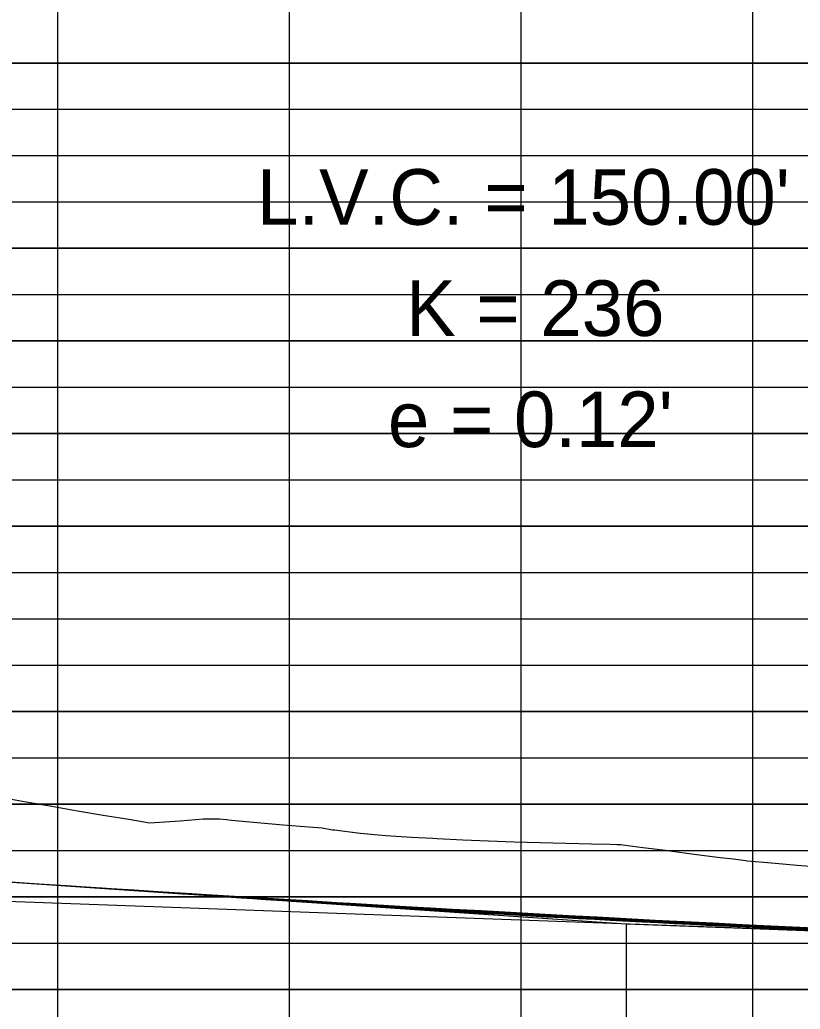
# Model space of a CAD drawing. Extents: x 1195880 to 1289360, y 2059330 to 2086925.
# Drawn here: x 1197302.3 to 1197386.5, y 2059658.6 to 2059765.4 of the extents above; entities that cross this region are included whole.
import ezdxf

# ---------------------------------------------------------------- set-up
doc = ezdxf.new("R2010")
doc.units = 0
for name, color, linetype in [('Default', 7, 'Continuous'), ('Existing Ground PGL', 7, 'Continuous'), ('Grid', 7, 'Continuous'), ('Profile', 7, 'Continuous'), ('Profile Annotation', 7, 'Continuous')]:
    doc.layers.add(name, color=color, linetype=linetype)

msp = doc.modelspace()

# ---------------------------------------------------------------- linework, layer by layer
for p, q in [((1197188.59, 2059680.04), (1197367.71, 2059667.81)), ((1197188.59, 2059680.04), (1197367.71, 2059667.81)), ((1197253.56, 2059675.6), (1197367.71, 2059667.81)), ((1197253.56, 2059675.6), (1197326.4, 2059670.63)), ((1197253.56, 2059675.6), (1197317.71, 2059671.22)), ((1197253.56, 2059675.6), (1197323.22, 2059670.85)), ((1197253.56, 2059675.6), (1197322.71, 2059670.88)), ((1197253.56, 2059675.6), (1197317.71, 2059671.22)), ((1197253.56, 2059675.6), (1197320.21, 2059671.05)), ((1197263.59, 2059674.92), (1197320.21, 2059671.05)), ((1197268.59, 2059674.58), (1197320.21, 2059671.05)), ((1197273.59, 2059674.23), (1197320.21, 2059671.05)), ((1197273.59, 2059674.23), (1197307.21, 2059671.94)), ((1197273.59, 2059674.23), (1197305.21, 2059672.08)), ((1197273.59, 2059674.23), (1197302.71, 2059672.25)), ((1197367.71, 2059667.81), (1197516.64, 2059662.37)), ((1197367.71, 2059667.81), (1197516.64, 2059662.37)), ((1197367.71, 2059667.81), (1197516.64, 2059662.37))]:
    msp.add_line(p, q)
for points in [[(1197300.21, 2059672.42), (1197303.02, 2059672.23), (1197305.83, 2059672.04), (1197308.65, 2059671.85), (1197311.46, 2059671.66), (1197314.27, 2059671.48), (1197317.08, 2059671.3), (1197319.9, 2059671.12), (1197322.71, 2059670.94), (1197325.52, 2059670.76), (1197328.33, 2059670.59), (1197331.15, 2059670.42), (1197333.96, 2059670.25), (1197336.77, 2059670.08), (1197339.58, 2059669.91), (1197342.4, 2059669.75), (1197345.21, 2059669.58), (1197348.02, 2059669.42), (1197350.83, 2059669.26), (1197353.65, 2059669.1), (1197356.46, 2059668.95), (1197359.27, 2059668.79), (1197362.08, 2059668.64), (1197364.9, 2059668.49), (1197370.52, 2059668.2), (1197373.33, 2059668.05), (1197376.15, 2059667.91), (1197378.96, 2059667.77), (1197381.77, 2059667.63), (1197384.58, 2059667.49), (1197387.4, 2059667.36)], [(1197300.63, 2059672.39), (1197303.54, 2059672.19), (1197306.46, 2059672), (1197309.38, 2059671.81), (1197312.29, 2059671.62), (1197315.21, 2059671.43), (1197318.13, 2059671.24), (1197321.04, 2059671.06), (1197323.96, 2059670.87), (1197326.88, 2059670.69), (1197329.79, 2059670.51), (1197332.71, 2059670.34), (1197335.63, 2059670.16), (1197338.54, 2059669.99), (1197341.46, 2059669.82), (1197344.38, 2059669.65), (1197347.29, 2059669.48), (1197350.21, 2059669.32), (1197353.13, 2059669.15), (1197356.04, 2059668.99), (1197358.96, 2059668.83), (1197361.88, 2059668.67), (1197364.79, 2059668.52), (1197370.63, 2059668.21), (1197373.54, 2059668.06), (1197376.46, 2059667.91), (1197379.38, 2059667.77), (1197382.29, 2059667.62), (1197385.21, 2059667.48), (1197388.13, 2059667.34)], [(1197301.25, 2059672.35), (1197304.27, 2059672.15), (1197307.29, 2059671.95), (1197310.31, 2059671.75), (1197313.33, 2059671.56), (1197316.36, 2059671.36), (1197319.38, 2059671.17), (1197322.4, 2059670.98), (1197325.42, 2059670.8), (1197328.44, 2059670.61), (1197331.46, 2059670.43), (1197334.48, 2059670.25), (1197337.5, 2059670.07), (1197340.52, 2059669.89), (1197343.54, 2059669.71), (1197346.56, 2059669.54), (1197349.58, 2059669.37), (1197352.61, 2059669.2), (1197355.63, 2059669.03), (1197358.65, 2059668.87), (1197361.67, 2059668.7), (1197364.69, 2059668.54), (1197370.73, 2059668.23), (1197373.75, 2059668.07), (1197376.77, 2059667.92), (1197379.79, 2059667.77), (1197382.81, 2059667.62), (1197385.83, 2059667.47), (1197388.86, 2059667.32)], [(1197302.08, 2059672.3), (1197305.21, 2059672.09), (1197308.33, 2059671.89), (1197311.46, 2059671.69), (1197314.58, 2059671.49), (1197317.71, 2059671.29), (1197320.83, 2059671.09), (1197323.96, 2059670.9), (1197327.08, 2059670.71), (1197330.21, 2059670.52), (1197333.33, 2059670.33), (1197336.46, 2059670.14), (1197339.58, 2059669.96), (1197342.71, 2059669.78), (1197345.83, 2059669.6), (1197348.96, 2059669.42), (1197352.08, 2059669.25), (1197355.21, 2059669.08), (1197358.33, 2059668.9), (1197361.46, 2059668.74), (1197364.58, 2059668.57), (1197370.83, 2059668.24), (1197373.96, 2059668.08), (1197377.08, 2059667.92), (1197380.21, 2059667.77), (1197383.33, 2059667.61), (1197386.46, 2059667.46), (1197389.58, 2059667.31)], [(1197302.16, 2059672.29), (1197305.14, 2059672.09), (1197308.12, 2059671.89), (1197311.1, 2059671.7), (1197314.08, 2059671.51), (1197317.06, 2059671.31), (1197320.04, 2059671.13), (1197323.02, 2059670.94), (1197326, 2059670.75), (1197328.98, 2059670.57), (1197331.96, 2059670.39), (1197334.94, 2059670.21), (1197337.92, 2059670.04), (1197340.9, 2059669.86), (1197343.87, 2059669.69), (1197346.85, 2059669.52), (1197349.83, 2059669.35), (1197352.81, 2059669.18), (1197355.79, 2059669.02), (1197358.77, 2059668.85), (1197361.75, 2059668.69), (1197364.73, 2059668.53), (1197370.69, 2059668.22), (1197373.67, 2059668.07), (1197376.65, 2059667.92), (1197379.63, 2059667.77), (1197382.61, 2059667.62), (1197385.59, 2059667.47), (1197388.57, 2059667.33)], [(1197302.71, 2059672.25), (1197305.42, 2059672.06), (1197308.13, 2059671.88), (1197310.83, 2059671.7), (1197313.54, 2059671.52), (1197316.25, 2059671.34), (1197318.96, 2059671.17), (1197321.67, 2059671), (1197324.38, 2059670.82), (1197327.08, 2059670.65), (1197329.79, 2059670.49), (1197332.5, 2059670.32), (1197335.21, 2059670.16), (1197337.92, 2059669.99), (1197340.63, 2059669.83), (1197343.33, 2059669.67), (1197346.04, 2059669.52), (1197348.75, 2059669.36), (1197351.46, 2059669.21), (1197354.17, 2059669.06), (1197356.88, 2059668.91), (1197359.58, 2059668.76), (1197362.29, 2059668.61), (1197365, 2059668.47), (1197370.42, 2059668.18), (1197373.13, 2059668.04), (1197375.83, 2059667.91), (1197378.54, 2059667.77), (1197381.25, 2059667.64), (1197383.96, 2059667.51), (1197386.67, 2059667.37)], [(1197305.21, 2059672.08), (1197307.81, 2059671.9), (1197310.42, 2059671.72), (1197313.02, 2059671.55), (1197315.63, 2059671.38), (1197318.23, 2059671.21), (1197320.83, 2059671.04), (1197323.44, 2059670.87), (1197326.04, 2059670.71), (1197328.65, 2059670.54), (1197331.25, 2059670.38), (1197333.86, 2059670.22), (1197336.46, 2059670.07), (1197339.06, 2059669.91), (1197341.67, 2059669.75), (1197344.27, 2059669.6), (1197346.88, 2059669.45), (1197349.48, 2059669.3), (1197352.08, 2059669.15), (1197354.69, 2059669.01), (1197357.29, 2059668.86), (1197359.9, 2059668.72), (1197362.5, 2059668.58), (1197365.11, 2059668.44), (1197370.31, 2059668.17), (1197372.92, 2059668.03), (1197375.52, 2059667.9), (1197378.13, 2059667.77), (1197380.73, 2059667.64), (1197383.33, 2059667.52), (1197385.94, 2059667.39), (1197388.54, 2059667.27)], [(1197307.21, 2059671.94), (1197309.73, 2059671.77), (1197312.25, 2059671.6), (1197314.77, 2059671.43), (1197317.29, 2059671.26), (1197319.81, 2059671.1), (1197322.33, 2059670.94), (1197324.86, 2059670.77), (1197327.38, 2059670.62), (1197329.9, 2059670.46), (1197332.42, 2059670.3), (1197334.94, 2059670.15), (1197337.46, 2059669.99), (1197339.98, 2059669.84), (1197342.5, 2059669.69), (1197345.02, 2059669.54), (1197347.54, 2059669.4), (1197350.06, 2059669.25), (1197352.58, 2059669.11), (1197355.11, 2059668.97), (1197357.63, 2059668.83), (1197360.15, 2059668.69), (1197362.67, 2059668.56), (1197365.19, 2059668.42), (1197370.23, 2059668.16), (1197372.75, 2059668.03), (1197375.27, 2059667.9), (1197377.79, 2059667.77), (1197380.31, 2059667.65), (1197382.83, 2059667.53), (1197385.36, 2059667.4), (1197387.88, 2059667.29)], [(1197317.71, 2059671.22), (1197319.79, 2059671.08), (1197321.88, 2059670.94), (1197323.96, 2059670.8), (1197326.04, 2059670.66), (1197328.13, 2059670.53), (1197330.21, 2059670.39), (1197332.29, 2059670.26), (1197334.38, 2059670.13), (1197336.46, 2059670), (1197338.54, 2059669.87), (1197340.63, 2059669.74), (1197342.71, 2059669.61), (1197344.79, 2059669.49), (1197346.88, 2059669.37), (1197348.96, 2059669.24), (1197351.04, 2059669.12), (1197353.13, 2059669), (1197355.21, 2059668.88), (1197357.29, 2059668.77), (1197359.38, 2059668.65), (1197361.46, 2059668.54), (1197363.54, 2059668.43), (1197365.63, 2059668.31), (1197369.79, 2059668.1), (1197371.88, 2059667.99), (1197373.96, 2059667.88), (1197376.04, 2059667.78), (1197378.13, 2059667.68), (1197380.21, 2059667.57), (1197382.29, 2059667.47), (1197384.38, 2059667.38), (1197386.46, 2059667.28), (1197388.54, 2059667.18)], [(1197317.71, 2059671.22), (1197319.79, 2059671.08), (1197321.88, 2059670.94), (1197323.96, 2059670.8), (1197326.04, 2059670.66), (1197328.13, 2059670.53), (1197330.21, 2059670.39), (1197332.29, 2059670.26), (1197334.38, 2059670.13), (1197336.46, 2059670), (1197338.54, 2059669.87), (1197340.63, 2059669.74), (1197342.71, 2059669.61), (1197344.79, 2059669.49), (1197346.88, 2059669.37), (1197348.96, 2059669.24), (1197351.04, 2059669.12), (1197353.13, 2059669), (1197355.21, 2059668.88), (1197357.29, 2059668.77), (1197359.38, 2059668.65), (1197361.46, 2059668.54), (1197363.54, 2059668.43), (1197365.63, 2059668.31), (1197369.79, 2059668.1), (1197371.88, 2059667.99), (1197373.96, 2059667.88), (1197376.04, 2059667.78), (1197378.13, 2059667.68), (1197380.21, 2059667.57), (1197382.29, 2059667.47), (1197384.38, 2059667.38), (1197386.46, 2059667.28), (1197388.54, 2059667.18)], [(1197320.21, 2059671.05), (1197322.19, 2059670.92), (1197324.17, 2059670.78), (1197326.15, 2059670.65), (1197328.13, 2059670.52), (1197330.11, 2059670.39), (1197332.08, 2059670.26), (1197334.06, 2059670.14), (1197336.04, 2059670.01), (1197338.02, 2059669.89), (1197340, 2059669.77), (1197341.98, 2059669.64), (1197343.96, 2059669.52), (1197345.94, 2059669.4), (1197347.92, 2059669.29), (1197349.9, 2059669.17), (1197351.88, 2059669.06), (1197353.86, 2059668.94), (1197355.83, 2059668.83), (1197357.81, 2059668.72), (1197359.79, 2059668.61), (1197361.77, 2059668.5), (1197363.75, 2059668.4), (1197365.73, 2059668.29), (1197369.69, 2059668.08), (1197371.67, 2059667.98), (1197373.65, 2059667.88), (1197375.63, 2059667.78), (1197377.61, 2059667.68), (1197379.58, 2059667.59), (1197381.56, 2059667.49), (1197383.54, 2059667.4), (1197385.52, 2059667.31), (1197387.5, 2059667.21)], [(1197320.21, 2059671.05), (1197322.19, 2059670.92), (1197324.17, 2059670.78), (1197326.15, 2059670.65), (1197328.13, 2059670.52), (1197330.11, 2059670.39), (1197332.08, 2059670.26), (1197334.06, 2059670.14), (1197336.04, 2059670.01), (1197338.02, 2059669.89), (1197340, 2059669.77), (1197341.98, 2059669.64), (1197343.96, 2059669.52), (1197345.94, 2059669.4), (1197347.92, 2059669.29), (1197349.9, 2059669.17), (1197351.88, 2059669.06), (1197353.86, 2059668.94), (1197355.83, 2059668.83), (1197357.81, 2059668.72), (1197359.79, 2059668.61), (1197361.77, 2059668.5), (1197363.75, 2059668.4), (1197365.73, 2059668.29), (1197369.69, 2059668.08), (1197371.67, 2059667.98), (1197373.65, 2059667.88), (1197375.63, 2059667.78), (1197377.61, 2059667.68), (1197379.58, 2059667.59), (1197381.56, 2059667.49), (1197383.54, 2059667.4), (1197385.52, 2059667.31), (1197387.5, 2059667.21)], [(1197320.21, 2059671.05), (1197322.19, 2059670.92), (1197324.17, 2059670.78), (1197326.15, 2059670.65), (1197328.13, 2059670.52), (1197330.11, 2059670.39), (1197332.08, 2059670.26), (1197334.06, 2059670.14), (1197336.04, 2059670.01), (1197338.02, 2059669.89), (1197340, 2059669.77), (1197341.98, 2059669.64), (1197343.96, 2059669.52), (1197345.94, 2059669.4), (1197347.92, 2059669.29), (1197349.9, 2059669.17), (1197351.88, 2059669.06), (1197353.86, 2059668.94), (1197355.83, 2059668.83), (1197357.81, 2059668.72), (1197359.79, 2059668.61), (1197361.77, 2059668.5), (1197363.75, 2059668.4), (1197365.73, 2059668.29), (1197369.69, 2059668.08), (1197371.67, 2059667.98), (1197373.65, 2059667.88), (1197375.63, 2059667.78), (1197377.61, 2059667.68), (1197379.58, 2059667.59), (1197381.56, 2059667.49), (1197383.54, 2059667.4), (1197385.52, 2059667.31), (1197387.5, 2059667.21)], [(1197320.21, 2059671.05), (1197322.19, 2059670.92), (1197324.17, 2059670.78), (1197326.15, 2059670.65), (1197328.13, 2059670.52), (1197330.11, 2059670.39), (1197332.08, 2059670.26), (1197334.06, 2059670.14), (1197336.04, 2059670.01), (1197338.02, 2059669.89), (1197340, 2059669.77), (1197341.98, 2059669.64), (1197343.96, 2059669.52), (1197345.94, 2059669.4), (1197347.92, 2059669.29), (1197349.9, 2059669.17), (1197351.88, 2059669.06), (1197353.86, 2059668.94), (1197355.83, 2059668.83), (1197357.81, 2059668.72), (1197359.79, 2059668.61), (1197361.77, 2059668.5), (1197363.75, 2059668.4), (1197365.73, 2059668.29), (1197369.69, 2059668.08), (1197371.67, 2059667.98), (1197373.65, 2059667.88), (1197375.63, 2059667.78), (1197377.61, 2059667.68), (1197379.58, 2059667.59), (1197381.56, 2059667.49), (1197383.54, 2059667.4), (1197385.52, 2059667.31), (1197387.5, 2059667.21)], [(1197322.71, 2059670.88), (1197324.58, 2059670.75), (1197326.46, 2059670.63), (1197328.33, 2059670.5), (1197330.21, 2059670.38), (1197332.08, 2059670.26), (1197333.96, 2059670.13), (1197335.83, 2059670.01), (1197337.71, 2059669.9), (1197339.58, 2059669.78), (1197341.46, 2059669.66), (1197343.33, 2059669.55), (1197345.21, 2059669.43), (1197347.08, 2059669.32), (1197348.96, 2059669.21), (1197350.83, 2059669.1), (1197352.71, 2059668.99), (1197354.58, 2059668.88), (1197356.46, 2059668.78), (1197358.33, 2059668.67), (1197360.21, 2059668.57), (1197362.08, 2059668.47), (1197363.96, 2059668.36), (1197365.83, 2059668.26), (1197369.58, 2059668.07), (1197371.46, 2059667.97), (1197373.33, 2059667.88), (1197375.21, 2059667.78), (1197377.08, 2059667.69), (1197378.96, 2059667.6), (1197380.83, 2059667.51), (1197382.71, 2059667.42), (1197384.58, 2059667.33), (1197386.46, 2059667.25), (1197388.33, 2059667.16)], [(1197323.22, 2059670.85), (1197325.07, 2059670.72), (1197326.93, 2059670.59), (1197328.78, 2059670.47), (1197330.63, 2059670.35), (1197332.49, 2059670.23), (1197334.34, 2059670.11), (1197336.19, 2059669.99), (1197338.05, 2059669.87), (1197339.9, 2059669.76), (1197341.76, 2059669.64), (1197343.61, 2059669.53), (1197345.46, 2059669.42), (1197347.32, 2059669.3), (1197349.17, 2059669.19), (1197351.03, 2059669.09), (1197352.88, 2059668.98), (1197354.73, 2059668.87), (1197356.59, 2059668.77), (1197358.44, 2059668.66), (1197360.29, 2059668.56), (1197362.15, 2059668.46), (1197364, 2059668.36), (1197365.86, 2059668.26), (1197369.56, 2059668.06), (1197371.42, 2059667.97), (1197373.27, 2059667.88), (1197375.13, 2059667.78), (1197376.98, 2059667.69), (1197378.83, 2059667.6), (1197380.69, 2059667.51), (1197382.54, 2059667.42), (1197384.39, 2059667.34), (1197386.25, 2059667.25), (1197388.1, 2059667.17)], [(1197326.4, 2059670.63), (1197328.12, 2059670.51), (1197329.84, 2059670.4), (1197331.56, 2059670.28), (1197333.28, 2059670.17), (1197335, 2059670.06), (1197336.72, 2059669.94), (1197338.45, 2059669.83), (1197340.17, 2059669.72), (1197341.89, 2059669.62), (1197343.61, 2059669.51), (1197345.33, 2059669.4), (1197347.05, 2059669.3), (1197348.77, 2059669.2), (1197350.5, 2059669.09), (1197352.22, 2059668.99), (1197353.94, 2059668.89), (1197355.66, 2059668.8), (1197357.38, 2059668.7), (1197359.1, 2059668.6), (1197360.82, 2059668.51), (1197362.55, 2059668.41), (1197364.27, 2059668.32), (1197365.99, 2059668.23), (1197369.43, 2059668.05), (1197371.15, 2059667.96), (1197372.87, 2059667.87), (1197374.6, 2059667.78), (1197376.32, 2059667.7), (1197378.04, 2059667.62), (1197379.76, 2059667.53), (1197381.48, 2059667.45), (1197383.2, 2059667.37), (1197384.92, 2059667.29), (1197386.65, 2059667.21)]]:
    msp.add_lwpolyline(points)
at = {"layer": 'Default'}
msp.add_line((1197516.64, 2059662.37), (1197260.22, 2059671.73), dxfattribs=at)
at = {"layer": 'Existing Ground PGL'}
msp.add_lwpolyline([(1197300.16, 2059681.51), (1197302.93, 2059681), (1197305.7, 2059680.51), (1197308.48, 2059680.03), (1197311.25, 2059679.57), (1197314.02, 2059679.11), (1197316.26, 2059678.72), (1197316.8, 2059678.76), (1197319.57, 2059678.96), (1197322.03, 2059679.16), (1197322.34, 2059679.16), (1197323.81, 2059679.15), (1197324.55, 2059679.08), (1197325.12, 2059679.02), (1197327.89, 2059678.76), (1197330.67, 2059678.52), (1197333.44, 2059678.29), (1197334.9, 2059678.18), (1197336.01, 2059677.99), (1197336.21, 2059677.97), (1197338.99, 2059677.61), (1197339.03, 2059677.6), (1197340.94, 2059677.42), (1197341.76, 2059677.37), (1197344.54, 2059677.19), (1197346.82, 2059677.06), (1197347.31, 2059677.04), (1197350.09, 2059676.9), (1197352.86, 2059676.79), (1197355.63, 2059676.68), (1197358.41, 2059676.6), (1197361.18, 2059676.52), (1197362.6, 2059676.5), (1197363.96, 2059676.46), (1197365.99, 2059676.43), (1197366.73, 2059676.39), (1197367.08, 2059676.38), (1197368.43, 2059676.22), (1197369.5, 2059676.08), (1197372.28, 2059675.73), (1197372.43, 2059675.71), (1197375.05, 2059675.36), (1197377.83, 2059675), (1197379.24, 2059674.83), (1197380.6, 2059674.65), (1197380.77, 2059674.63), (1197383.38, 2059674.4), (1197386.15, 2059674.16), (1197388.92, 2059673.94)], dxfattribs=at)
at = {"layer": 'Grid'}
for p, q in [((1197306.37, 2059350.74), (1197306.37, 2059950.74)), ((1197331.37, 2059350.74), (1197331.37, 2059950.74)), ((1197356.37, 2059350.74), (1197356.37, 2059950.74)), ((1197381.37, 2059350.74), (1197381.37, 2059950.74)), ((1197006.37, 2059760.74), (1198006.37, 2059760.74)), ((1198006.37, 2059760.74), (1197006.37, 2059760.74)), ((1197006.37, 2059755.74), (1198006.37, 2059755.74)), ((1197006.37, 2059750.74), (1198006.37, 2059750.74)), ((1197006.37, 2059745.74), (1198006.37, 2059745.74)), ((1197006.37, 2059740.74), (1198006.37, 2059740.74)), ((1198006.37, 2059740.74), (1197006.37, 2059740.74)), ((1197006.37, 2059735.74), (1198006.37, 2059735.74)), ((1197006.37, 2059730.74), (1198006.37, 2059730.74)), ((1198006.37, 2059730.74), (1197006.37, 2059730.74)), ((1197006.37, 2059725.74), (1198006.37, 2059725.74)), ((1197006.37, 2059720.74), (1198006.37, 2059720.74)), ((1198006.37, 2059720.74), (1197006.37, 2059720.74)), ((1197006.37, 2059715.74), (1198006.37, 2059715.74)), ((1197006.37, 2059710.74), (1198006.37, 2059710.74)), ((1198006.37, 2059710.74), (1197006.37, 2059710.74)), ((1197006.37, 2059705.74), (1198006.37, 2059705.74)), ((1197006.37, 2059700.74), (1198006.37, 2059700.74)), ((1197006.37, 2059695.74), (1198006.37, 2059695.74)), ((1197006.37, 2059690.74), (1198006.37, 2059690.74)), ((1198006.37, 2059690.74), (1197006.37, 2059690.74)), ((1197006.37, 2059685.74), (1198006.37, 2059685.74)), ((1197006.37, 2059680.74), (1198006.37, 2059680.74)), ((1198006.37, 2059680.74), (1197006.37, 2059680.74)), ((1197006.37, 2059675.74), (1198006.37, 2059675.74)), ((1197006.37, 2059670.74), (1198006.37, 2059670.74)), ((1198006.37, 2059670.74), (1197006.37, 2059670.74)), ((1197006.37, 2059665.74), (1198006.37, 2059665.74)), ((1197006.37, 2059660.74), (1198006.37, 2059660.74)), ((1198006.37, 2059660.74), (1197006.37, 2059660.74))]:
    msp.add_line(p, q, dxfattribs=at)
at = {"layer": 'Profile'}
msp.add_lwpolyline([(1197302.08, 2059672.3), (1197305.21, 2059672.09), (1197308.33, 2059671.89), (1197311.46, 2059671.69), (1197314.58, 2059671.49), (1197317.71, 2059671.29), (1197320.83, 2059671.09), (1197323.96, 2059670.9), (1197327.08, 2059670.71), (1197330.21, 2059670.52), (1197333.33, 2059670.33), (1197336.46, 2059670.14), (1197339.58, 2059669.96), (1197342.71, 2059669.78), (1197345.83, 2059669.6), (1197348.96, 2059669.42), (1197352.08, 2059669.25), (1197355.21, 2059669.08), (1197358.33, 2059668.9), (1197361.46, 2059668.74), (1197364.58, 2059668.57), (1197370.83, 2059668.24), (1197373.96, 2059668.08), (1197377.08, 2059667.92), (1197380.21, 2059667.77), (1197383.33, 2059667.61), (1197386.46, 2059667.46), (1197389.58, 2059667.31)], dxfattribs=at)
at = {"layer": 'Profile Annotation'}
for p, q in [((1197330.21, 2059670.37), (1197367.71, 2059667.81)), ((1197367.71, 2059667.81), (1197405.21, 2059666.44)), ((1197367.71, 2059667.81), (1197367.71, 2059567.81))]:
    msp.add_line(p, q, dxfattribs=at)

# ---------------------------------------------------------------- texts
for s, p in [("L.V.C. = 150.00'", (1197327.86, 2059743.28)), ('K = 236', (1197343.95, 2059731.28)), ("e = 0.12'", (1197341.99, 2059719.28))]:
    msp.add_text(s, height=6, dxfattribs=at).set_placement(p)

doc.saveas('drawing.dxf')
